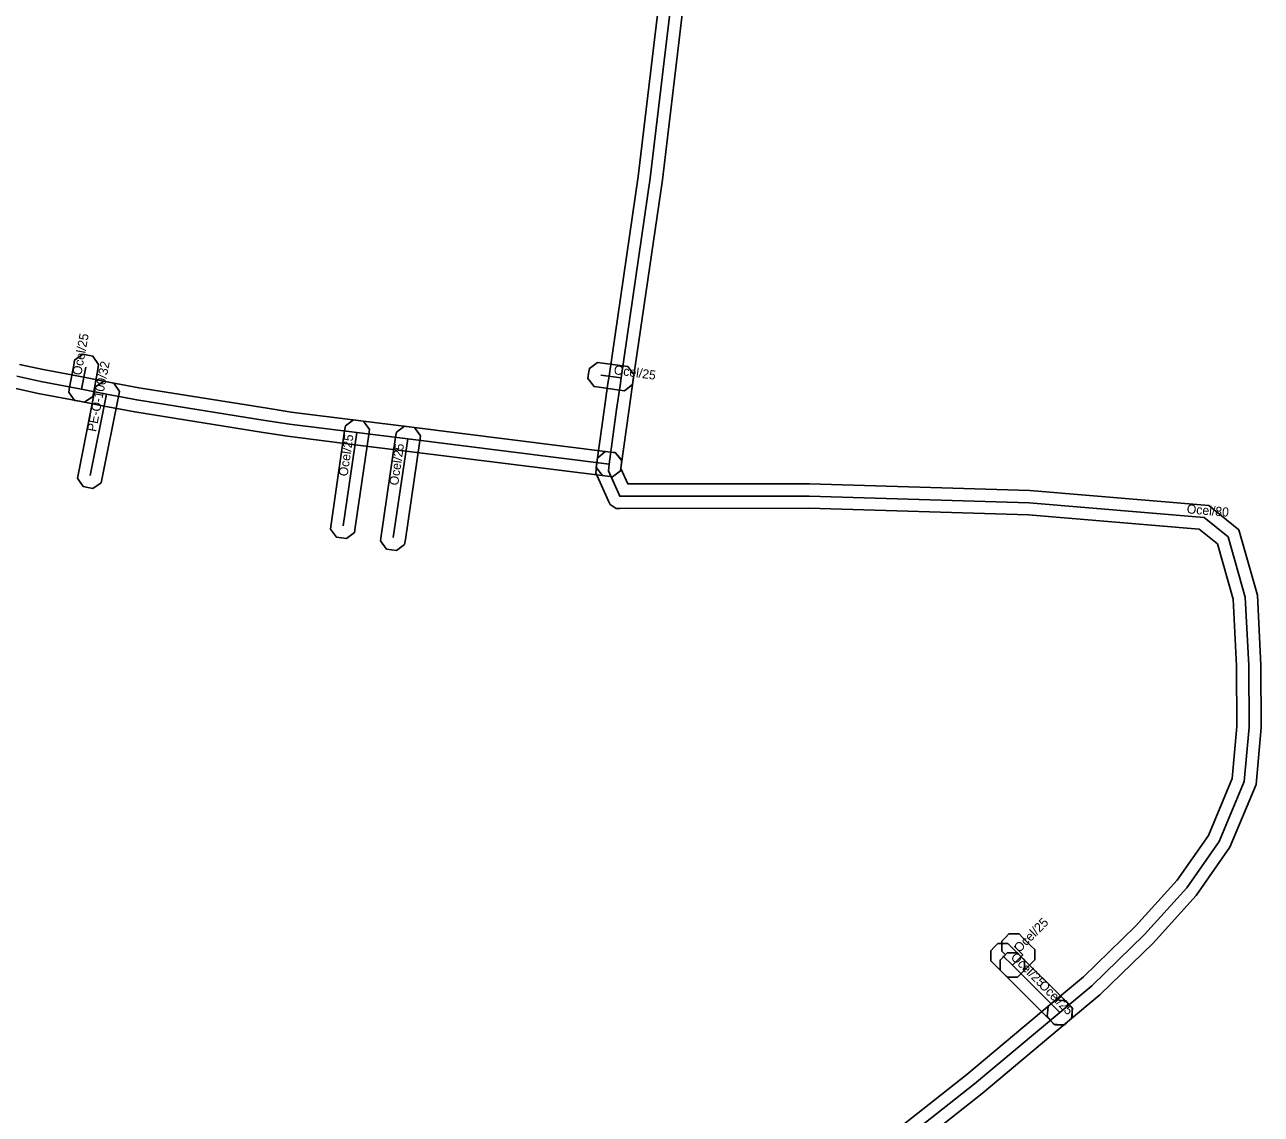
# Model space of a CAD drawing. Extents: x -569373 to -565022, y -1135090 to -1131496.
# Drawn here: x -565298.7 to -565197.4, y -1133935.9 to -1133846.6 of the extents above; entities that cross this region are included whole.
import ezdxf

# ---------------------------------------------------------------- set-up
doc = ezdxf.new("R2010")
doc.units = 0
for name, color, linetype in [('1', 7, 'Continuous'), ('24', 7, 'Continuous'), ('30', 7, 'Continuous')]:
    doc.layers.add(name, color=color, linetype=linetype)

msp = doc.modelspace()

# ---------------------------------------------------------------- linework, layer by layer
at = {"layer": '1'}
for points in [[(-565244.517, -1133842.748), (-565245.126, -1133847.877), (-565246.489, -1133859.351), (-565248.881, -1133875.735), (-565248.97, -1133876.342), (-565249.246, -1133878.319), (-565249.87, -1133882.798), (-565249.927, -1133883.208), (-565250.588, -1133883.707), (-565250.998, -1133883.65), (-565251.408, -1133883.593), (-565251.907, -1133882.932), (-565251.85, -1133882.522), (-565251.226, -1133878.043), (-565250.95, -1133876.058), (-565250.859, -1133875.445), (-565248.471, -1133859.089), (-565247.112, -1133847.641), (-565246.573, -1133843.104)], [(-565299.167, -1133874.476), (-565297.229, -1133874.9), (-565293.892, -1133875.538), (-565291.863, -1133875.928), (-565289.387, -1133876.405), (-565278.882, -1133878.077), (-565276.919, -1133878.39), (-565271.416, -1133879.078), (-565267.236, -1133879.598), (-565250.736, -1133881.668), (-565250.325, -1133881.719), (-565249.816, -1133882.373), (-565249.868, -1133882.784), (-565249.919, -1133883.195), (-565250.573, -1133883.704), (-565250.984, -1133883.652), (-565267.484, -1133881.582), (-565271.664, -1133881.062), (-565277.201, -1133880.37), (-565279.196, -1133880.053), (-565289.733, -1133878.375), (-565292.241, -1133877.892), (-565294.268, -1133877.502), (-565297.631, -1133876.86), (-565299.595, -1133876.43)], [(-565228.66, -1133938.295), (-565221.541, -1133932.674), (-565214.562, -1133926.833), (-565214.244, -1133926.567), (-565213.419, -1133926.64), (-565213.153, -1133926.958), (-565212.887, -1133927.276), (-565212.96, -1133928.101), (-565213.278, -1133928.367), (-565220.279, -1133934.226), (-565227.42, -1133939.865)]]:
    msp.add_lwpolyline(points, dxfattribs=at)
for points in [[(-565295.138, -1133876.748), (-565295.064, -1133876.341), (-565294.734, -1133874.531), (-565294.659, -1133874.123), (-565293.978, -1133873.652), (-565293.571, -1133873.726), (-565293.163, -1133873.801), (-565292.692, -1133874.482), (-565292.766, -1133874.889), (-565293.096, -1133876.699), (-565293.171, -1133877.107), (-565293.852, -1133877.578), (-565294.259, -1133877.504), (-565294.667, -1133877.429)], [(-565249.596, -1133876.637), (-565250.006, -1133876.581), (-565251.676, -1133876.351), (-565252.086, -1133876.294), (-565252.587, -1133875.634), (-565252.531, -1133875.224), (-565252.474, -1133874.814), (-565251.814, -1133874.313), (-565251.404, -1133874.369), (-565249.734, -1133874.599), (-565249.324, -1133874.656), (-565248.823, -1133875.316), (-565248.879, -1133875.726), (-565248.936, -1133876.136)], [(-565290.991, -1133876.698), (-565291.071, -1133877.104), (-565292.389, -1133883.774), (-565292.469, -1133884.18), (-565293.158, -1133884.641), (-565293.564, -1133884.561), (-565293.97, -1133884.481), (-565294.431, -1133883.792), (-565294.351, -1133883.386), (-565293.033, -1133876.716), (-565292.953, -1133876.31), (-565292.264, -1133875.849), (-565291.858, -1133875.929), (-565291.452, -1133876.009)], [(-565270.491, -1133879.804), (-565270.55, -1133880.214), (-565271.66, -1133887.854), (-565271.72, -1133888.264), (-565272.384, -1133888.759), (-565272.794, -1133888.7), (-565273.204, -1133888.64), (-565273.699, -1133887.976), (-565273.64, -1133887.566), (-565272.53, -1133879.926), (-565272.47, -1133879.516), (-565271.806, -1133879.021), (-565271.396, -1133879.08), (-565270.986, -1133879.14)], [(-565266.31, -1133880.324), (-565266.37, -1133880.734), (-565267.55, -1133888.824), (-565267.61, -1133889.234), (-565268.274, -1133889.73), (-565268.684, -1133889.67), (-565269.094, -1133889.61), (-565269.59, -1133888.946), (-565269.53, -1133888.536), (-565268.35, -1133880.446), (-565268.29, -1133880.036), (-565267.626, -1133879.54), (-565267.216, -1133879.6), (-565266.806, -1133879.66)], [(-565249.825, -1133882.341), (-565249.864, -1133882.754), (-565249.89, -1133883.023), (-565249.331, -1133884.28), (-565234.445, -1133884.27), (-565216.373, -1133884.821), (-565201.709, -1133886.049), (-565199.255, -1133888.042), (-565197.727, -1133893.396), (-565197.44, -1133899.142), (-565197.41, -1133904.252), (-565197.828, -1133908.903), (-565199.979, -1133914.054), (-565202.736, -1133918.004), (-565206.27, -1133921.904), (-565210.629, -1133926.153), (-565213.279, -1133928.367), (-565213.597, -1133928.633), (-565214.421, -1133928.559), (-565214.687, -1133928.241), (-565214.953, -1133927.923), (-565214.879, -1133927.099), (-565214.561, -1133926.833), (-565211.971, -1133924.667), (-565207.71, -1133920.516), (-565204.304, -1133916.756), (-565201.741, -1133913.086), (-565199.792, -1133908.417), (-565199.41, -1133904.168), (-565199.44, -1133899.198), (-565199.713, -1133893.724), (-565201.005, -1133889.198), (-565202.491, -1133887.991), (-565216.487, -1133886.819), (-565234.475, -1133886.27), (-565249.979, -1133886.28), (-565250.275, -1133886.28), (-565250.773, -1133885.957), (-565250.894, -1133885.687), (-565251.93, -1133883.357), (-565251.856, -1133882.566), (-565251.817, -1133882.153), (-565251.179, -1133881.625), (-565250.766, -1133881.664), (-565250.353, -1133881.703)], [(-565218.517, -1133923.003), (-565218.379, -1133922.865), (-565218.667, -1133922.581), (-565218.673, -1133921.753), (-565218.382, -1133921.458), (-565218.091, -1133921.163), (-565217.263, -1133921.157), (-565216.968, -1133921.448), (-565216.258, -1133922.148), (-565215.961, -1133922.44), (-565215.96, -1133922.856), (-565215.959, -1133923.273), (-565216.253, -1133923.567), (-565217.103, -1133924.417), (-565217.396, -1133924.71), (-565218.224, -1133924.71), (-565218.517, -1133924.417), (-565218.81, -1133924.124), (-565218.81, -1133923.296)], [(-565218.217, -1133924.713), (-565218.512, -1133924.422), (-565219.282, -1133923.662), (-565219.577, -1133923.371), (-565219.583, -1133922.543), (-565219.292, -1133922.248), (-565219.001, -1133921.953), (-565218.173, -1133921.947), (-565217.878, -1133922.238), (-565217.108, -1133922.998), (-565216.813, -1133923.289), (-565216.807, -1133924.117), (-565217.098, -1133924.412), (-565217.389, -1133924.707)], [(-565214.334, -1133928.6), (-565214.627, -1133928.307), (-565218.517, -1133924.417), (-565218.81, -1133924.124), (-565218.81, -1133923.296), (-565218.517, -1133923.003), (-565218.224, -1133922.71), (-565217.396, -1133922.71), (-565217.103, -1133923.003), (-565213.213, -1133926.893), (-565212.92, -1133927.186), (-565212.92, -1133928.014), (-565213.213, -1133928.307), (-565213.506, -1133928.6)]]:
    msp.add_lwpolyline(points, close=True, dxfattribs=at)
at = {"layer": '24'}
for points in [[(-565250.86, -1133882.66), (-565250.236, -1133878.181), (-565249.96, -1133876.2), (-565249.87, -1133875.59), (-565247.48, -1133859.22), (-565246.119, -1133847.759), (-565245.603, -1133843.414), (-565245.51, -1133842.63), (-565249.25, -1133839.99), (-565258.01, -1133833.81), (-565267.04, -1133827.44), (-565283.8, -1133815.61), (-565295.87, -1133808.73), (-565304.33, -1133805.81), (-565313.48, -1133802.66), (-565322.87, -1133796.68)], [(-565294.08, -1133876.52), (-565293.75, -1133874.71)], [(-565299.381, -1133875.453), (-565297.43, -1133875.88), (-565294.08, -1133876.52), (-565292.052, -1133876.91), (-565289.56, -1133877.39), (-565279.039, -1133879.065), (-565277.06, -1133879.38), (-565271.54, -1133880.07), (-565267.36, -1133880.59), (-565250.86, -1133882.66)], [(-565249.87, -1133875.59), (-565251.54, -1133875.36)], [(-565292.052, -1133876.91), (-565293.37, -1133883.58)], [(-565271.54, -1133880.07), (-565272.65, -1133887.71)], [(-565267.36, -1133880.59), (-565268.54, -1133888.68)], [(-565250.86, -1133882.66), (-565250.91, -1133883.19), (-565249.98, -1133885.28), (-565234.46, -1133885.27), (-565216.43, -1133885.82), (-565202.1, -1133887.02), (-565200.13, -1133888.62), (-565198.72, -1133893.56), (-565198.44, -1133899.17), (-565198.41, -1133904.21), (-565198.81, -1133908.66), (-565200.86, -1133913.57), (-565203.52, -1133917.38), (-565206.99, -1133921.21), (-565211.3, -1133925.41), (-565213.92, -1133927.6)], [(-565217.81, -1133923.71), (-565216.96, -1133922.86), (-565217.67, -1133922.16)], [(-565217.81, -1133923.71), (-565218.58, -1133922.95)], [(-565213.92, -1133927.6), (-565217.81, -1133923.71)], [(-565213.92, -1133927.6), (-565220.91, -1133933.45), (-565228.04, -1133939.08), (-565231.97, -1133942.18), (-565233.16, -1133943.11), (-565242.73, -1133950.58), (-565257.41, -1133962.12), (-565278.16, -1133958.62), (-565278.88, -1133958.49)]]:
    msp.add_lwpolyline(points, dxfattribs=at)

# ---------------------------------------------------------------- texts
at = {"layer": '30'}
for s, rotation, p in [('Ocel/25', 79.6673, (-565294.115, -1133875.415)), ('PE-O-100/32', 78.82228, (-565292.911, -1133880.045)), ('Ocel/25', 352.1583, (-565250.505, -1133875.275)), ('Ocel/25', 81.73345, (-565272.295, -1133883.69)), ('Ocel/25', 81.70141, (-565268.15, -1133884.435)), ('Ocel/80', 355.2132, (-565203.539, -1133886.683)), ('Ocel/25', 45, (-565217.232, -1133922.732)), ('Ocel/25', 315.37448, (-565217.995, -1133923.13)), ('Ocel/25', 315, (-565215.7, -1133925.42))]:
    msp.add_text(s, height=0.75, rotation=rotation, dxfattribs=at).set_placement(p)

doc.saveas('drawing.dxf')
